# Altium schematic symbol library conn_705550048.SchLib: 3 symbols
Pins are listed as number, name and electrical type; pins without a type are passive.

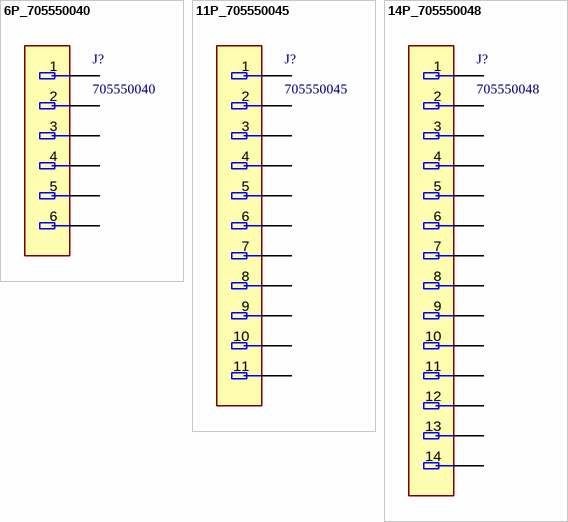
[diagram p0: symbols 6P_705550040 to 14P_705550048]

## 6P_705550040
designator J?, comment 705550040
Connector Header Through Hole, Right Angle 6 position 0.100" (2.54mm)
footprint 705550040 (Footprint not found)
pins: 1, 2, 3, 4, 5, 6

## 11P_705550045
designator J?, comment 705550045
Connector Header Through Hole, Right Angle 11 position 0.100" (2.54mm)
footprint 705550045 (Footprint not found)
pins: 1, 2, 3, 4, 5, 6, 7, 8, 9, 10, 11

## 14P_705550048
designator J?, comment 705550048
Connector Header Through Hole, Right Angle 14 position 0.100" (2.54mm)
footprint 705550048
pins: 1, 2, 3, 4, 5, 6, 7, 8, 9, 10, 11, 12, 13, 14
